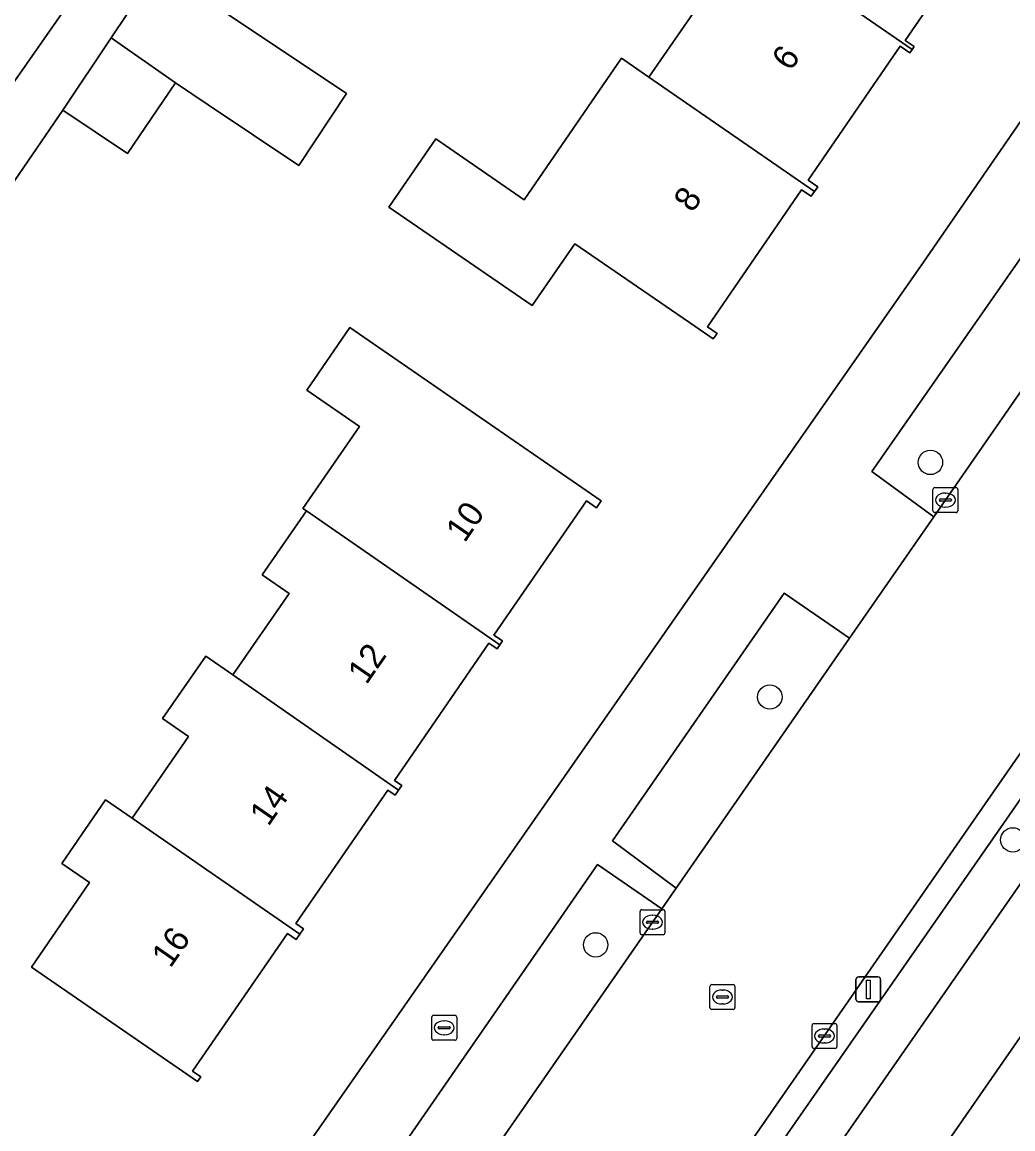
# Model space of a CAD drawing. Extents: x 160157 to 160921, y 381516 to 382045.
# Drawn here: x 160703.18 to 160742.95, y 381715.22 to 381759.62 of the extents above; entities that cross this region are included whole.
import ezdxf

# ---------------------------------------------------------------- set-up
doc = ezdxf.new("R2010")
doc.units = 0
for name, color, linetype in [('IMGEO_Berm_groen', 7, 'Continuous'), ('IMGEO_Boom', 7, 'Continuous'), ('IMGEO_Brandkraan', 7, 'Continuous'), ('IMGEO_Erf', 7, 'Continuous'), ('IMGEO_Fietspad_open', 7, 'Continuous'), ('IMGEO_Groenvoorziening', 7, 'Continuous'), ('IMGEO_Kolk', 7, 'Continuous'), ('IMGEO_Lichtmast', 7, 'Continuous'), ('IMGEO_Pand', 7, 'Continuous'), ('IMGEO_Pand_nummerreeks', 7, 'Continuous'), ('IMGEO_Rijbaan_lokaal_open', 7, 'Continuous'), ('IMGEO_Rioolput', 7, 'Continuous'), ('IMGEO_Voetpad_open', 7, 'Continuous')]:
    doc.layers.add(name, color=color, linetype=linetype)

msp = doc.modelspace()

# ---------------------------------------------------------------- linework, layer by layer
at = {"layer": 'IMGEO_Berm_groen'}
for points in [[(160746.867, 381750), (160749.312, 381753.522), (160746.826, 381755.275), (160743.151, 381750), (160737.292, 381741.592), (160739.771, 381739.776)], [(160736.392, 381734.908), (160733.773, 381736.719), (160726.88, 381726.772), (160729.43, 381724.878)], [(160747.881, 381731.718), (160745.595, 381731.832), (160742.577, 381727.467), (160725.874, 381703.49), (160727.474, 381702.387)], [(160728.855, 381724.049), (160726.28, 381725.823), (160716.892, 381712.283), (160719.444, 381710.49)]]:
    msp.add_lwpolyline(points, close=True, dxfattribs=at)
at = {"layer": 'IMGEO_Boom'}
for centre in [(160739.639, 381741.96), (160733.193, 381732.548), (160742.946, 381726.817), (160726.2, 381722.604)]:
    msp.add_circle(centre, 0.489, dxfattribs=at)
at = {"layer": 'IMGEO_Brandkraan'}
for p, q in [((160719.623, 381718.852), (160719.623, 381719.704)), ((160719.698, 381719.778), (160720.55, 381719.778)), ((160720.111, 381719.558), (160720.136, 381719.558)), ((160720.624, 381719.704), (160720.624, 381718.852)), ((160719.882, 381719.272), (160719.882, 381719.284)), ((160720.32, 381719.235), (160719.922, 381719.235)), ((160719.925, 381719.321), (160720.323, 381719.321)), ((160720.366, 381719.284), (160720.366, 381719.272)), ((160720.55, 381718.778), (160719.698, 381718.778)), ((160720.134, 381718.998), (160720.109, 381718.998))]:
    msp.add_line(p, q, dxfattribs=at)
for points in [[(160719.623, 381718.852), (160719.623, 381719.704)], [(160719.698, 381719.778), (160720.55, 381719.778)], [(160720.624, 381719.704), (160720.624, 381718.852)], [(160720.55, 381718.778), (160719.698, 381718.778)]]:
    msp.add_lwpolyline(points, dxfattribs=at)
for centre, radius, start, end in [((160719.7, 381719.702), 0.0765, 91.552, 178.448), ((160719.7, 381719.702), 0.0765, 91.552, 178.448), ((160720.548, 381719.702), 0.0765, 1.552, 88.448), ((160720.548, 381719.702), 0.0765, 1.552, 88.448), ((160719.922, 381719.281), 0.0403, 85.8775, 175.7526), ((160719.919, 381719.271), 0.0366, 178.938, 274.7102), ((160720.323, 381719.278), 0.043, 264.8664, 352.4533), ((160720.327, 381719.283), 0.0386, 1.7309, 96.639), ((160719.7, 381718.854), 0.0765, 181.552, 268.448), ((160719.7, 381718.854), 0.0765, 181.552, 268.448), ((160720.548, 381718.854), 0.0765, 271.552, 358.448), ((160720.548, 381718.854), 0.0765, 271.552, 358.448)]:
    msp.add_arc(centre, radius, start, end, dxfattribs=at)
for centre, major_axis, ratio, start_param, end_param in [((160720.11, 381719.278), (-0.387, 0.002), 0.722429, 4.712389, 7.853982), ((160720.135, 381719.278), (-0.39, 0.002), 0.717154, 1.570796, 4.712389)]:
    msp.add_ellipse(centre, major_axis=major_axis, ratio=ratio, start_param=start_param, end_param=end_param, dxfattribs=at)
at = {"layer": 'IMGEO_Erf'}
for points in [[(160664.019, 381641.292), (160689.395, 381678.051), (160693.253, 381683.64), (160710.372, 381708.438), (160712.255, 381711.149), (160713.812, 381713.39), (160731.28, 381738.425), (160734.718, 381743.353), (160739.356, 381750), (160751.191, 381767.158)], [(160742.481, 381764.494), (160738.63, 381758.892), (160738.985, 381758.648), (160738.9, 381758.523), (160738.813, 381758.397), (160738.423, 381758.666), (160734.726, 381753.288), (160735.116, 381753.02), (160734.985, 381752.83), (160734.853, 381752.639), (160734.468, 381752.903), (160730.684, 381747.4), (160731.072, 381747.134), (160730.921, 381746.914), (160730.176, 381747.426), (160725.365, 381750.734), (160723.659, 381748.25), (160717.904, 381752.204), (160719.781, 381754.937), (160723.333, 381752.498), (160727.237, 381758.177), (160728.339, 381757.419), (160730.593, 381760.699)], [(160674.255, 381763.205), (160683.384, 381756.947), (160693.336, 381750.054), (160694.595, 381749.193), (160697.153, 381752.885), (160696.309, 381753.463), (160698.157, 381756.131), (160699.531, 381758.115), (160702.195, 381756.292), (160706.329, 381762.2)], [(160708.643, 381761.815), (160716.195, 381756.759), (160714.289, 381753.867), (160710.649, 381756.304), (160709.333, 381757.185), (160707.408, 381754.355), (160704.812, 381756.094), (160700.486, 381749.785), (160698.405, 381746.884), (160701.182, 381744.89), (160699.277, 381742.162), (160701.542, 381740.58), (160699.671, 381737.974), (160694.615, 381741.604), (160688.937, 381733.695), (160687.172, 381734.933), (160688.607, 381736.98), (160685.787, 381738.957), (160687.849, 381741.899), (160690.669, 381739.922), (160693.419, 381743.844), (160688.458, 381747.248), (160690.156, 381749.722), (160673.051, 381761.449)]]:
    msp.add_lwpolyline(points, dxfattribs=at)
msp.add_lwpolyline([(160714.59, 381740.013), (160714.454, 381740.106), (160716.727, 381743.402), (160714.607, 381744.863), (160716.341, 381747.379), (160726.427, 381740.424), (160726.231, 381740.141), (160725.83, 381740.417), (160722.119, 381735.035), (160722.464, 381734.798), (160722.353, 381734.639), (160722.245, 381734.481), (160721.92, 381734.704), (160718.127, 381729.204), (160718.418, 381729.003), (160718.282, 381728.807), (160718.149, 381728.613), (160717.857, 381728.814), (160714.168, 381723.464), (160714.477, 381723.251), (160714.327, 381723.035), (160714.177, 381722.818), (160713.828, 381723.059), (160710.021, 381717.536), (160710.347, 381717.311), (160710.215, 381717.12), (160703.554, 381721.713), (160705.891, 381725.102), (160704.774, 381725.872), (160706.529, 381728.417), (160707.596, 381727.681), (160709.861, 381730.965), (160708.821, 381731.682), (160710.551, 381734.189), (160711.644, 381733.435), (160713.899, 381736.705), (160712.822, 381737.448)], close=True, dxfattribs=at)
at = {"layer": 'IMGEO_Fietspad_open'}
msp.add_lwpolyline([(160701.965, 381659.446), (160707.599, 381667.561), (160715.353, 381678.728), (160750.884, 381729.902), (160753.579, 381733.814), (160764.918, 381750), (160767.517, 381753.72), (160791.434, 381788.016), (160792.763, 381789.478), (160789.665, 381791.308), (160769.212, 381762.274), (160768.522, 381761.29), (160761.166, 381750.794), (160760.618, 381750), (160750.493, 381735.463), (160747.881, 381731.718), (160727.474, 381702.387), (160726.771, 381701.377), (160705.315, 381670.539), (160704.668, 381669.608), (160697.946, 381659.948)], dxfattribs=at)
at = {"layer": 'IMGEO_Groenvoorziening'}
msp.add_lwpolyline([(160761.696, 381722.771), (160752.602, 381728.769), (160752.505, 381728.833), (160750.884, 381729.902), (160715.353, 381678.728), (160707.599, 381667.561), (160701.965, 381659.446), (160701.931, 381659.132)], dxfattribs=at)
at = {"layer": 'IMGEO_Kolk'}
for p, q in [((160739.738, 381740.024), (160739.738, 381740.876)), ((160739.813, 381740.95), (160740.665, 381740.95)), ((160740.739, 381740.876), (160740.739, 381740.024)), ((160739.997, 381740.444), (160739.997, 381740.456)), ((160740.435, 381740.407), (160740.037, 381740.407)), ((160740.04, 381740.493), (160740.438, 381740.493)), ((160740.226, 381740.73), (160740.251, 381740.73)), ((160740.481, 381740.456), (160740.481, 381740.444)), ((160740.665, 381739.95), (160739.813, 381739.95)), ((160740.249, 381740.17), (160740.224, 381740.17)), ((160727.982, 381723.087), (160727.982, 381723.939)), ((160728.057, 381724.013), (160728.909, 381724.013)), ((160728.983, 381723.939), (160728.983, 381723.087)), ((160728.241, 381723.507), (160728.241, 381723.519)), ((160728.679, 381723.47), (160728.281, 381723.47)), ((160728.284, 381723.556), (160728.682, 381723.556)), ((160728.47, 381723.793), (160728.495, 381723.793)), ((160728.725, 381723.519), (160728.725, 381723.507)), ((160728.909, 381723.013), (160728.057, 381723.013)), ((160728.493, 381723.233), (160728.468, 381723.233)), ((160734.886, 381718.521), (160734.886, 381719.373)), ((160734.961, 381719.447), (160735.813, 381719.447)), ((160735.374, 381719.227), (160735.399, 381719.227)), ((160735.887, 381719.373), (160735.887, 381718.521)), ((160735.145, 381718.941), (160735.145, 381718.953)), ((160735.583, 381718.904), (160735.185, 381718.904)), ((160735.188, 381718.99), (160735.586, 381718.99)), ((160735.397, 381718.667), (160735.372, 381718.667)), ((160735.629, 381718.953), (160735.629, 381718.941)), ((160735.813, 381718.447), (160734.961, 381718.447))]:
    msp.add_line(p, q, dxfattribs=at)
for points in [[(160739.738, 381740.024), (160739.738, 381740.876)], [(160739.813, 381740.95), (160740.665, 381740.95)], [(160740.739, 381740.876), (160740.739, 381740.024)], [(160740.665, 381739.95), (160739.813, 381739.95)], [(160727.982, 381723.087), (160727.982, 381723.939)], [(160728.057, 381724.013), (160728.909, 381724.013)], [(160728.983, 381723.939), (160728.983, 381723.087)], [(160728.909, 381723.013), (160728.057, 381723.013)], [(160734.886, 381718.521), (160734.886, 381719.373)], [(160734.961, 381719.447), (160735.813, 381719.447)], [(160735.887, 381719.373), (160735.887, 381718.521)], [(160735.813, 381718.447), (160734.961, 381718.447)]]:
    msp.add_lwpolyline(points, dxfattribs=at)
for centre, radius, start, end in [((160739.815, 381740.874), 0.0765, 91.552, 178.448), ((160739.815, 381740.874), 0.0765, 91.552, 178.448), ((160740.663, 381740.874), 0.0765, 1.552, 88.448), ((160740.663, 381740.874), 0.0765, 1.552, 88.448), ((160740.037, 381740.453), 0.0403, 85.8775, 175.7526), ((160740.034, 381740.443), 0.0366, 178.938, 274.7102), ((160740.438, 381740.45), 0.043, 264.8664, 352.4533), ((160740.442, 381740.455), 0.0386, 1.7309, 96.639), ((160739.815, 381740.026), 0.0765, 181.552, 268.448), ((160739.815, 381740.026), 0.0765, 181.552, 268.448), ((160740.663, 381740.026), 0.0765, 271.552, 358.448), ((160740.663, 381740.026), 0.0765, 271.552, 358.448), ((160728.059, 381723.937), 0.0765, 91.552, 178.448), ((160728.059, 381723.937), 0.0765, 91.552, 178.448), ((160728.907, 381723.937), 0.0765, 1.552, 88.448), ((160728.907, 381723.937), 0.0765, 1.552, 88.448), ((160728.281, 381723.516), 0.0403, 85.8775, 175.7526), ((160728.278, 381723.506), 0.0366, 178.938, 274.7102), ((160728.682, 381723.513), 0.043, 264.8664, 352.4533), ((160728.686, 381723.518), 0.0386, 1.7309, 96.639), ((160728.059, 381723.089), 0.0765, 181.552, 268.448), ((160728.059, 381723.089), 0.0765, 181.552, 268.448), ((160728.907, 381723.089), 0.0765, 271.552, 358.448), ((160728.907, 381723.089), 0.0765, 271.552, 358.448), ((160734.963, 381719.371), 0.0765, 91.552, 178.448), ((160734.963, 381719.371), 0.0765, 91.552, 178.448), ((160735.811, 381719.371), 0.0765, 1.552, 88.448), ((160735.811, 381719.371), 0.0765, 1.552, 88.448), ((160735.185, 381718.95), 0.0403, 85.8775, 175.7526), ((160735.182, 381718.94), 0.0366, 178.938, 274.7102), ((160735.586, 381718.947), 0.043, 264.8664, 352.4533), ((160735.59, 381718.952), 0.0386, 1.7309, 96.639), ((160734.963, 381718.523), 0.0765, 181.552, 268.448), ((160734.963, 381718.523), 0.0765, 181.552, 268.448), ((160735.811, 381718.523), 0.0765, 271.552, 358.448), ((160735.811, 381718.523), 0.0765, 271.552, 358.448)]:
    msp.add_arc(centre, radius, start, end, dxfattribs=at)
for centre, major_axis, ratio, start_param, end_param in [((160740.225, 381740.45), (-0.387, 0.002), 0.722429, 4.712389, 7.853982), ((160740.25, 381740.45), (-0.39, 0.002), 0.717154, 1.570796, 4.712389), ((160728.469, 381723.513), (-0.387, 0.002), 0.722429, 4.712389, 7.853982), ((160728.494, 381723.513), (-0.39, 0.002), 0.717154, 1.570796, 4.712389), ((160735.373, 381718.947), (-0.387, 0.002), 0.722429, 4.712389, 7.853982), ((160735.398, 381718.947), (-0.39, 0.002), 0.717154, 1.570796, 4.712389)]:
    msp.add_ellipse(centre, major_axis=major_axis, ratio=ratio, start_param=start_param, end_param=end_param, dxfattribs=at)
at = {"layer": 'IMGEO_Lichtmast'}
for p, q in [((160736.749, 381721.318), (160737.539, 381721.318)), ((160737.539, 381721.318), (160736.749, 381721.318)), ((160736.649, 381720.418), (160736.649, 381721.218)), ((160736.649, 381721.218), (160736.649, 381720.418)), ((160737.639, 381721.218), (160737.639, 381720.418)), ((160737.639, 381720.418), (160737.639, 381721.218)), ((160737.539, 381720.318), (160736.749, 381720.318)), ((160736.749, 381720.318), (160737.539, 381720.318))]:
    msp.add_line(p, q, dxfattribs=at)
msp.add_lwpolyline([(160737.069, 381721.193), (160737.219, 381721.193), (160737.219, 381720.443), (160737.069, 381720.443), (160737.069, 381721.193)], dxfattribs=at)
for centre, start, end in [((160736.749, 381721.218), 90, 180), ((160736.749, 381721.218), 90, 180), ((160737.539, 381721.218), 0, 90), ((160737.539, 381721.218), 360, 90), ((160736.749, 381720.418), 180, 270), ((160736.749, 381720.418), 180, 270), ((160737.539, 381720.418), 270, 0), ((160737.539, 381720.418), 270, 0)]:
    msp.add_arc(centre, 0.1, start, end, dxfattribs=at)
at = {"layer": 'IMGEO_Pand'}
for points in [[(160732.259, 381763.116), (160738.9, 381758.523), (160738.985, 381758.648), (160738.63, 381758.892), (160742.481, 381764.494), (160742.832, 381764.253), (160742.941, 381764.412), (160736.285, 381768.99), (160735.18, 381769.69), (160733.492, 381767.235), (160734.577, 381766.489)], [(160734.985, 381752.83), (160735.116, 381753.02), (160734.726, 381753.288), (160738.423, 381758.666), (160738.813, 381758.397), (160738.9, 381758.523), (160732.259, 381763.116), (160731.19, 381763.851), (160729.527, 381761.432), (160730.593, 381760.699), (160728.339, 381757.419)], [(160709.333, 381757.185), (160710.649, 381756.304), (160714.289, 381753.867), (160716.195, 381756.759), (160708.643, 381761.815), (160706.757, 381758.998)], [(160709.333, 381757.185), (160706.757, 381758.998), (160704.812, 381756.094), (160707.408, 381754.355)], [(160734.985, 381752.83), (160728.339, 381757.419), (160727.237, 381758.177), (160723.333, 381752.498), (160719.781, 381754.937), (160717.904, 381752.204), (160723.659, 381748.25), (160725.365, 381750.734), (160730.176, 381747.426), (160730.921, 381746.914), (160731.072, 381747.134), (160730.684, 381747.4), (160734.468, 381752.903), (160734.853, 381752.639)], [(160725.83, 381740.417), (160726.231, 381740.141), (160726.427, 381740.424), (160716.341, 381747.379), (160714.607, 381744.863), (160716.727, 381743.402), (160714.454, 381740.106), (160714.59, 381740.013), (160722.353, 381734.639), (160722.464, 381734.798), (160722.119, 381735.035)], [(160711.644, 381733.435), (160718.282, 381728.807), (160718.418, 381729.003), (160718.127, 381729.204), (160721.92, 381734.704), (160722.245, 381734.481), (160722.353, 381734.639), (160714.59, 381740.013), (160712.822, 381737.448), (160713.899, 381736.705)], [(160711.644, 381733.435), (160710.551, 381734.189), (160708.821, 381731.682), (160709.861, 381730.965), (160707.596, 381727.681), (160714.327, 381723.035), (160714.477, 381723.251), (160714.168, 381723.464), (160717.857, 381728.814), (160718.149, 381728.613), (160718.282, 381728.807)], [(160707.596, 381727.681), (160706.529, 381728.417), (160704.774, 381725.872), (160705.891, 381725.102), (160703.554, 381721.713), (160710.215, 381717.12), (160710.347, 381717.311), (160710.021, 381717.536), (160713.828, 381723.059), (160714.177, 381722.818), (160714.327, 381723.035)]]:
    msp.add_lwpolyline(points, close=True, dxfattribs=at)
at = {"layer": 'IMGEO_Rijbaan_lokaal_open'}
for points in [[(160669.597, 381624.241), (160673.052, 381629.169), (160742.168, 381728.75), (160744.459, 381732.031), (160749.187, 381738.841), (160756.939, 381750), (160765.763, 381763.144), (160772.954, 381773.374), (160774.36, 381775.443), (160780.995, 381784.58)], [(160766.774, 381775.383), (160764.783, 381775.027), (160764.22, 381774.643), (160763.193, 381773.21), (160756.409, 381763.749), (160749.93, 381754.413), (160749.312, 381753.522), (160746.867, 381750), (160739.771, 381739.776), (160736.392, 381734.908), (160729.43, 381724.878), (160728.855, 381724.049), (160719.444, 381710.49), (160715.092, 381704.22), (160708.66, 381694.953), (160708.147, 381694.213), (160698.421, 381680.201), (160694.523, 381674.586), (160688.846, 381666.406), (160687.489, 381664.451)], [(160751.191, 381767.158), (160739.356, 381750), (160734.718, 381743.353), (160731.28, 381738.425), (160713.812, 381713.39), (160716.493, 381711.643), (160716.892, 381712.283), (160726.28, 381725.823), (160728.855, 381724.049), (160729.43, 381724.878), (160726.88, 381726.772), (160733.773, 381736.719), (160736.392, 381734.908), (160739.771, 381739.776), (160737.292, 381741.592), (160743.151, 381750), (160746.826, 381755.275), (160749.312, 381753.522), (160749.93, 381754.413), (160747.407, 381756.134), (160753.795, 381765.515)]]:
    msp.add_lwpolyline(points, dxfattribs=at)
at = {"layer": 'IMGEO_Rioolput'}
for p, q in [((160730.79, 381720.086), (160730.79, 381720.938)), ((160730.865, 381721.012), (160731.717, 381721.012)), ((160731.278, 381720.792), (160731.303, 381720.792)), ((160731.791, 381720.938), (160731.791, 381720.086)), ((160731.049, 381720.506), (160731.049, 381720.518)), ((160731.487, 381720.469), (160731.089, 381720.469)), ((160731.092, 381720.555), (160731.49, 381720.555)), ((160731.533, 381720.518), (160731.533, 381720.506)), ((160731.717, 381720.012), (160730.865, 381720.012)), ((160731.301, 381720.232), (160731.276, 381720.232))]:
    msp.add_line(p, q, dxfattribs=at)
for points in [[(160730.79, 381720.086), (160730.79, 381720.938)], [(160730.865, 381721.012), (160731.717, 381721.012)], [(160731.791, 381720.938), (160731.791, 381720.086)], [(160731.717, 381720.012), (160730.865, 381720.012)]]:
    msp.add_lwpolyline(points, dxfattribs=at)
for centre, radius, start, end in [((160730.867, 381720.936), 0.0765, 91.552, 178.448), ((160730.867, 381720.936), 0.0765, 91.552, 178.448), ((160731.715, 381720.936), 0.0765, 1.552, 88.448), ((160731.715, 381720.936), 0.0765, 1.552, 88.448), ((160731.089, 381720.515), 0.0403, 85.8775, 175.7526), ((160731.086, 381720.505), 0.0366, 178.938, 274.7102), ((160731.49, 381720.512), 0.043, 264.8664, 352.4533), ((160731.494, 381720.517), 0.0386, 1.7309, 96.639), ((160730.867, 381720.088), 0.0765, 181.552, 268.448), ((160730.867, 381720.088), 0.0765, 181.552, 268.448), ((160731.715, 381720.088), 0.0765, 271.552, 358.448), ((160731.715, 381720.088), 0.0765, 271.552, 358.448)]:
    msp.add_arc(centre, radius, start, end, dxfattribs=at)
for centre, major_axis, ratio, start_param, end_param in [((160731.277, 381720.512), (-0.387, 0.002), 0.722429, 4.712389, 7.853982), ((160731.302, 381720.512), (-0.39, 0.002), 0.717154, 1.570796, 4.712389)]:
    msp.add_ellipse(centre, major_axis=major_axis, ratio=ratio, start_param=start_param, end_param=end_param, dxfattribs=at)
at = {"layer": 'IMGEO_Voetpad_open'}
for points in [[(160780.995, 381784.58), (160774.36, 381775.443), (160772.954, 381773.374), (160765.763, 381763.144), (160756.939, 381750), (160749.187, 381738.841), (160744.459, 381732.031), (160742.168, 381728.75), (160673.052, 381629.169)], [(160706.329, 381762.2), (160702.195, 381756.292), (160700.819, 381754.305), (160698.618, 381751.126), (160696.416, 381747.947), (160694.595, 381749.193), (160693.336, 381750.054), (160683.384, 381756.947), (160674.255, 381763.205)], [(160673.051, 381761.449), (160690.156, 381749.722), (160690.226, 381749.824), (160695.657, 381746.097), (160693.89, 381743.521), (160693.419, 381743.844), (160690.669, 381739.922), (160688.607, 381736.98), (160687.172, 381734.933), (160688.937, 381733.695), (160694.615, 381741.604), (160696.439, 381744.144), (160698.405, 381746.884), (160700.486, 381749.785), (160704.812, 381756.094), (160706.757, 381758.998), (160708.643, 381761.815)], [(160696.326, 381661.075), (160703.044, 381670.718), (160704.668, 381669.608), (160705.315, 381670.539), (160703.659, 381671.601), (160725.16, 381702.466), (160726.771, 381701.377), (160727.474, 381702.387), (160725.874, 381703.49), (160742.577, 381727.467), (160745.595, 381731.832), (160747.881, 381731.718), (160750.493, 381735.463), (160749.744, 381737.741), (160753.925, 381743.816), (160759.252, 381751.557)]]:
    msp.add_lwpolyline(points, dxfattribs=at)

# ---------------------------------------------------------------- texts
at = {"layer": 'IMGEO_Pand_nummerreeks'}
for s, rotation, p in [('6', 55.2301, (160734.023, 381757.619)), ('8', 55.2301, (160730.085, 381751.946)), ('10', 55.3133, (160720.941, 381738.704)), ('12', 55.313, (160717.001, 381733.011)), ('14', 55.313, (160713.066, 381727.324)), ('16', 55.313, (160709.129, 381721.636))]:
    msp.add_text(s, height=1, rotation=rotation, dxfattribs=at).set_placement(p)

doc.saveas('drawing.dxf')
